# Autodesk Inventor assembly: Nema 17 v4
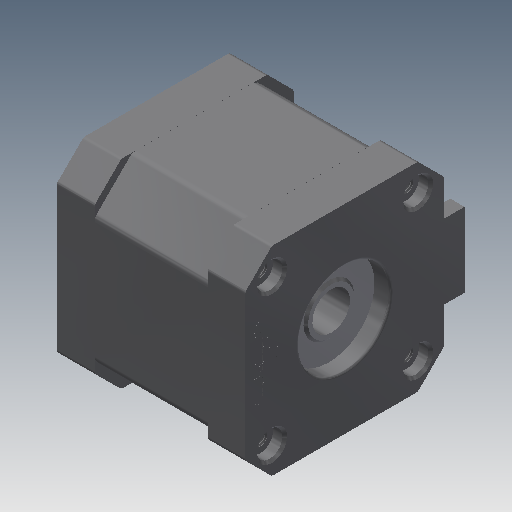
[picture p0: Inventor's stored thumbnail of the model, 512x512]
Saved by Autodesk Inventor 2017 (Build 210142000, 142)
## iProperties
Created: 2018-08
Part Number: Nema 17 v4
Document SubType Name: Assembly
Designer: JK
Author: JK
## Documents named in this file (2)
- C:\Users\JK\Documents\Inventor\BioExtruder\Nema 17 v4.iam
- C:\Users\JK\Documents\Inventor\BioExtruder\Nema 17 v7.iam
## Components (1 placed, 1 different names)
1. Nema 17 v7:1 [sub-assembly]
